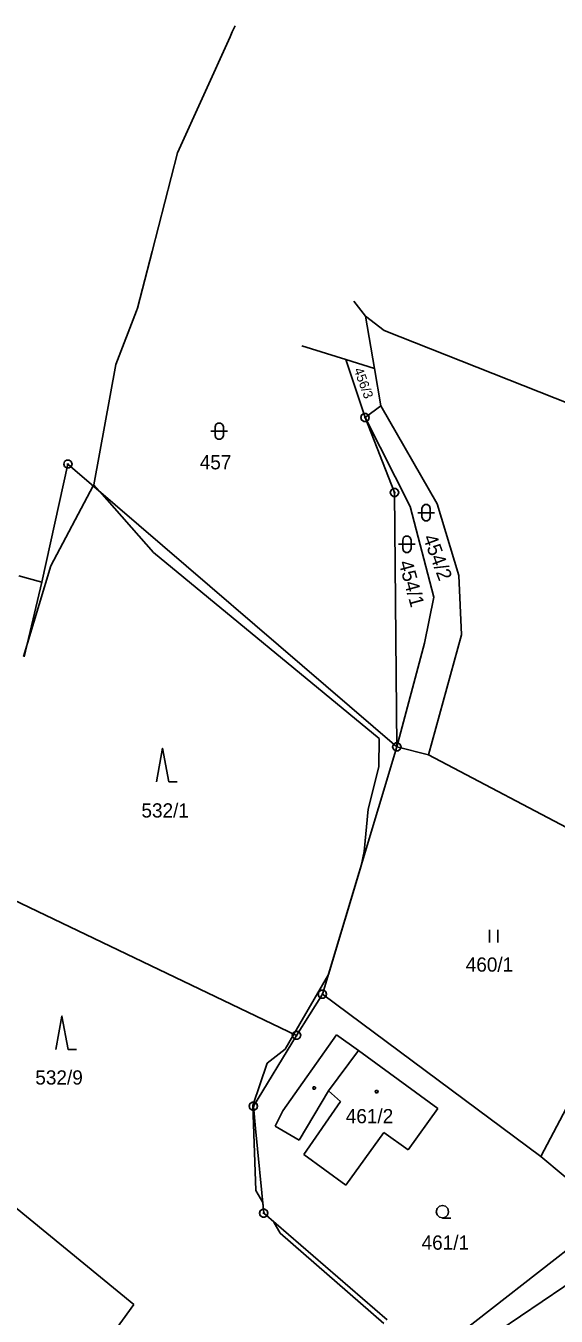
# Model space of a CAD drawing. Extents: x -759699 to -757730, y -1172308 to -1170857.
# Drawn here: x -759346 to -759282.5, y -1171711.2 to -1171556.8 of the extents above; entities that cross this region are included whole.
import ezdxf

# ---------------------------------------------------------------- set-up
doc = ezdxf.new("R2010")
doc.units = 0
for name, color, linetype in [('Vrstva 1', 7, 'Continuous'), ('Vrstva 11', 7, 'Continuous'), ('Vrstva 12', 7, 'Continuous'), ('Vrstva 2', 7, 'Continuous'), ('Vrstva 3', 7, 'Continuous'), ('Vrstva 4', 7, 'Continuous'), ('Vrstva 5', 7, 'Continuous'), ('Vrstva 8', 7, 'Continuous')]:
    doc.layers.add(name, color=color, linetype=linetype)

msp = doc.modelspace()

# ---------------------------------------------------------------- linework, layer by layer
at = {"layer": 'Vrstva 1'}
for p, q in [((-759305.37, -1171591.53), (-759306.74, -1171589.73)), ((-759306.74, -1171589.73), (-759306.74, -1171589.73)), ((-759303.12, -1171593.25), (-759305.37, -1171591.53)), ((-759305.37, -1171591.53), (-759304.29, -1171597.77)), ((-759264.92, -1171608.32), (-759303.12, -1171593.25)), ((-759312.98, -1171595.07), (-759312.98, -1171595.07)), ((-759312.98, -1171595.07), (-759307.69, -1171596.71)), ((-759307.69, -1171596.71), (-759304.29, -1171597.77)), ((-759307.69, -1171596.71), (-759305.41, -1171603.65)), ((-759304.29, -1171597.77), (-759303.52, -1171602.24)), ((-759303.52, -1171602.24), (-759305.41, -1171603.65)), ((-759303.52, -1171602.24), (-759296.79, -1171613.99)), ((-759305.41, -1171603.65), (-759300.01, -1171614.29)), ((-759305.41, -1171603.65), (-759305.41, -1171603.65)), ((-759301.87, -1171612.63), (-759305.41, -1171603.65)), ((-759344.12, -1171623.36), (-759340.98, -1171609.22)), ((-759340.98, -1171609.22), (-759340.98, -1171609.22)), ((-759340.98, -1171609.22), (-759301.6, -1171643.07)), ((-759301.6, -1171643.07), (-759301.87, -1171612.63)), ((-759296.79, -1171613.99), (-759294.16, -1171622.56)), ((-759300.01, -1171614.29), (-759297.16, -1171625.13)), ((-759346.22, -1171632.28), (-759344.12, -1171623.36)), ((-759294.16, -1171622.56), (-759293.86, -1171629.64)), ((-759297.16, -1171625.13), (-759298.3, -1171630.66)), ((-759298.3, -1171630.66), (-759301.6, -1171643.07)), ((-759293.86, -1171629.64), (-759297.81, -1171644)), ((-759310.51, -1171672.66), (-759301.6, -1171643.07)), ((-759297.81, -1171644), (-759301.6, -1171643.07)), ((-759297.81, -1171644), (-759262.18, -1171662.76)), ((-759351.15, -1171659.61), (-759313.61, -1171677.58)), ((-759310.51, -1171672.66), (-759313.61, -1171677.58)), ((-759284.37, -1171692.06), (-759310.51, -1171672.66)), ((-759276.45, -1171677.04), (-759284.37, -1171692.06)), ((-759313.61, -1171677.58), (-759318.78, -1171686.06)), ((-759308.84, -1171677.53), (-759315.24, -1171686.62)), ((-759306.2, -1171679.4), (-759308.84, -1171677.53)), ((-759296.68, -1171686.34), (-759306.2, -1171679.4)), ((-759364.55, -1171684.03), (-759333.09, -1171709.78)), ((-759313.29, -1171690.11), (-759309.78, -1171684.21)), ((-759309.78, -1171684.21), (-759308.36, -1171685.47)), ((-759318.78, -1171686.06), (-759318.52, -1171688.73)), ((-759315.24, -1171686.62), (-759316.16, -1171688.43)), ((-759308.36, -1171685.47), (-759312.73, -1171691.84)), ((-759300.26, -1171691.26), (-759296.68, -1171686.34)), ((-759318.52, -1171688.73), (-759317.54, -1171698.86)), ((-759316.16, -1171688.43), (-759313.29, -1171690.11)), ((-759307.7, -1171695.48), (-759303.17, -1171689.21)), ((-759303.17, -1171689.21), (-759300.26, -1171691.26)), ((-759312.73, -1171691.84), (-759307.7, -1171695.48)), ((-759284.37, -1171692.06), (-759275.95, -1171699.14)), ((-759317.54, -1171698.86), (-759302.74, -1171711.62)), ((-759297.8, -1171716.13), (-759275.95, -1171699.14)), ((-759347.86, -1171730.08), (-759333.09, -1171709.78))]:
    msp.add_line(p, q, dxfattribs=at)
at = {"layer": 'Vrstva 11'}
for p, q in [((-759320.97, -1171556.78), (-759321.31, -1171557.52)), ((-759321.57, -1171558.1), (-759327.86, -1171571.97)), ((-759321.31, -1171557.52), (-759321.57, -1171558.1)), ((-759327.86, -1171571.97), (-759330.91, -1171583.8)), ((-759330.91, -1171583.8), (-759332.05, -1171588.24)), ((-759332.05, -1171588.24), (-759332.65, -1171590.56)), ((-759332.76, -1171590.87), (-759335.24, -1171597.32)), ((-759332.65, -1171590.56), (-759332.76, -1171590.87)), ((-759335.24, -1171597.32), (-759337.88, -1171611.7)), ((-759343.03, -1171621.39), (-759337.95, -1171611.83)), ((-759337.95, -1171611.83), (-759337.88, -1171611.7)), ((-759337.88, -1171611.7), (-759337.17, -1171612.49)), ((-759337.17, -1171612.49), (-759330.72, -1171619.8)), ((-759330.72, -1171619.8), (-759303.72, -1171642.05)), ((-759345.84, -1171630.65), (-759343.03, -1171621.39)), ((-759346.32, -1171632.25), (-759345.84, -1171630.65)), ((-759303.72, -1171642.05), (-759303.74, -1171645.43)), ((-759303.74, -1171645.43), (-759305.05, -1171650.5)), ((-759305.05, -1171650.5), (-759305.5, -1171655.58)), ((-759305.5, -1171655.58), (-759305.88, -1171657.29)), ((-759305.88, -1171657.29), (-759309.8, -1171670.29)), ((-759309.8, -1171670.29), (-759313.94, -1171677.42)), ((-759313.94, -1171677.42), (-759314.99, -1171679.22)), ((-759314.99, -1171679.22), (-759317.12, -1171680.9)), ((-759317.12, -1171680.9), (-759318.85, -1171685.97)), ((-759318.85, -1171685.97), (-759318.5, -1171696.13)), ((-759318.5, -1171696.13), (-759317.66, -1171697.58)), ((-759317.66, -1171697.58), (-759317.54, -1171698.86)), ((-759317.54, -1171698.86), (-759316.33, -1171699.91)), ((-759316.33, -1171699.91), (-759315.56, -1171701.24)), ((-759315.56, -1171701.24), (-759303.17, -1171712.06))]:
    msp.add_line(p, q, dxfattribs=at)
at = {"layer": 'Vrstva 12'}
for p, q in [((-759309.78, -1171684.21), (-759306.2, -1171679.4)), ((-759296.68, -1171686.34), (-759306.2, -1171679.4)), ((-759309.78, -1171684.21), (-759308.36, -1171685.47)), ((-759308.36, -1171685.47), (-759312.73, -1171691.84)), ((-759300.26, -1171691.26), (-759296.68, -1171686.34)), ((-759307.7, -1171695.48), (-759303.17, -1171689.21)), ((-759303.17, -1171689.21), (-759300.26, -1171691.26)), ((-759312.73, -1171691.84), (-759307.7, -1171695.48))]:
    msp.add_line(p, q, dxfattribs=at)
at = {"layer": 'Vrstva 3'}
for p, q in [((-759290.49, -1171664.96), (-759290.49, -1171666.46)), ((-759289.49, -1171666.46), (-759289.49, -1171664.96))]:
    msp.add_line(p, q, dxfattribs=at)
for points in [[(-759323.37, -1171604.78), (-759323.27, -1171604.49), (-759323.02, -1171604.31), (-759322.71, -1171604.31), (-759322.46, -1171604.49), (-759322.36, -1171604.78), (-759322.36, -1171605.78), (-759322.46, -1171606.07), (-759322.71, -1171606.25), (-759323.02, -1171606.25), (-759323.27, -1171606.07), (-759323.37, -1171605.78)], [(-759298.6, -1171614.54), (-759298.5, -1171614.25), (-759298.25, -1171614.07), (-759297.94, -1171614.07), (-759297.69, -1171614.25), (-759297.59, -1171614.54), (-759297.59, -1171615.54), (-759297.69, -1171615.83), (-759297.94, -1171616.01), (-759298.25, -1171616.01), (-759298.5, -1171615.83), (-759298.6, -1171615.54)], [(-759300.9, -1171618.31), (-759300.8, -1171618.02), (-759300.55, -1171617.84), (-759300.24, -1171617.84), (-759299.99, -1171618.02), (-759299.89, -1171618.31), (-759299.89, -1171619.31), (-759299.99, -1171619.6), (-759300.24, -1171619.78), (-759300.55, -1171619.78), (-759300.8, -1171619.6), (-759300.9, -1171619.31)]]:
    msp.add_lwpolyline(points, close=True, dxfattribs=at)
for points in [[(-759323.87, -1171605.28), (-759322.6, -1171605.28), (-759321.87, -1171605.28)], [(-759299.1, -1171615.04), (-759297.83, -1171615.04), (-759297.1, -1171615.04)], [(-759301.4, -1171618.81), (-759300.13, -1171618.81), (-759299.4, -1171618.81)], [(-759330.39, -1171647.23), (-759329.64, -1171643.23), (-759328.89, -1171647.23), (-759327.89, -1171647.23)], [(-759342.45, -1171679.27), (-759341.7, -1171675.27), (-759340.95, -1171679.27), (-759339.95, -1171679.27)], [(-759296.13, -1171699.41), (-759296.51, -1171699.31), (-759296.78, -1171699.04), (-759296.88, -1171698.67), (-759296.78, -1171698.3), (-759296.51, -1171698.03), (-759296.14, -1171697.93), (-759295.77, -1171698.03), (-759295.5, -1171698.3), (-759295.4, -1171698.68), (-759295.5, -1171699.06), (-759295.77, -1171699.33), (-759296.15, -1171699.43), (-759295.15, -1171699.43)]]:
    msp.add_lwpolyline(points, dxfattribs=at)
at = {"layer": 'Vrstva 4'}
for p, q in [((-759346.85, -1171622.58), (-759344.12, -1171623.36)), ((-759309.78, -1171684.21), (-759306.2, -1171679.4)), ((-759296.25, -1171717.55), (-759273.85, -1171702.42))]:
    msp.add_line(p, q, dxfattribs=at)
at = {"layer": 'Vrstva 5'}
for points in [[(-759311.4, -1171683.73), (-759311.31, -1171683.88), (-759311.4, -1171684.03), (-759311.58, -1171684.03), (-759311.67, -1171683.88), (-759311.58, -1171683.73)], [(-759303.93, -1171684.16), (-759303.84, -1171684.31), (-759303.93, -1171684.46), (-759304.11, -1171684.46), (-759304.2, -1171684.31), (-759304.11, -1171684.16)]]:
    msp.add_lwpolyline(points, close=True, dxfattribs=at)
at = {"layer": 'Vrstva 8'}
for p, q in [((-759305.53, -1171603.65), (-759305.29, -1171603.65)), ((-759341.1, -1171609.22), (-759340.86, -1171609.22)), ((-759301.99, -1171612.63), (-759301.75, -1171612.63)), ((-759301.72, -1171643.07), (-759301.48, -1171643.07)), ((-759310.63, -1171672.66), (-759310.39, -1171672.66)), ((-759313.73, -1171677.58), (-759313.49, -1171677.58)), ((-759318.9, -1171686.06), (-759318.66, -1171686.06)), ((-759317.66, -1171698.86), (-759317.42, -1171698.86))]:
    msp.add_line(p, q, dxfattribs=at)
for points in [[(-759305.26, -1171603.17), (-759305.01, -1171603.35), (-759304.91, -1171603.64), (-759305.01, -1171603.93), (-759305.26, -1171604.11), (-759305.57, -1171604.11), (-759305.82, -1171603.93), (-759305.92, -1171603.64), (-759305.82, -1171603.35), (-759305.57, -1171603.17)], [(-759340.83, -1171608.74), (-759340.58, -1171608.92), (-759340.48, -1171609.21), (-759340.58, -1171609.5), (-759340.83, -1171609.68), (-759341.14, -1171609.68), (-759341.39, -1171609.5), (-759341.49, -1171609.21), (-759341.39, -1171608.92), (-759341.14, -1171608.74)], [(-759301.72, -1171612.15), (-759301.47, -1171612.33), (-759301.37, -1171612.62), (-759301.47, -1171612.91), (-759301.72, -1171613.09), (-759302.03, -1171613.09), (-759302.28, -1171612.91), (-759302.38, -1171612.62), (-759302.28, -1171612.33), (-759302.03, -1171612.15)], [(-759301.45, -1171642.59), (-759301.2, -1171642.77), (-759301.1, -1171643.06), (-759301.2, -1171643.35), (-759301.45, -1171643.53), (-759301.76, -1171643.53), (-759302.01, -1171643.35), (-759302.11, -1171643.06), (-759302.01, -1171642.77), (-759301.76, -1171642.59)], [(-759310.36, -1171672.18), (-759310.11, -1171672.36), (-759310.01, -1171672.65), (-759310.11, -1171672.94), (-759310.36, -1171673.12), (-759310.67, -1171673.12), (-759310.92, -1171672.94), (-759311.02, -1171672.65), (-759310.92, -1171672.36), (-759310.67, -1171672.18)], [(-759313.46, -1171677.1), (-759313.21, -1171677.28), (-759313.11, -1171677.57), (-759313.21, -1171677.86), (-759313.46, -1171678.04), (-759313.77, -1171678.04), (-759314.02, -1171677.86), (-759314.12, -1171677.57), (-759314.02, -1171677.28), (-759313.77, -1171677.1)], [(-759318.63, -1171685.58), (-759318.38, -1171685.76), (-759318.28, -1171686.05), (-759318.38, -1171686.34), (-759318.63, -1171686.52), (-759318.94, -1171686.52), (-759319.19, -1171686.34), (-759319.29, -1171686.05), (-759319.19, -1171685.76), (-759318.94, -1171685.58)], [(-759317.39, -1171698.38), (-759317.14, -1171698.56), (-759317.04, -1171698.85), (-759317.14, -1171699.14), (-759317.39, -1171699.32), (-759317.7, -1171699.32), (-759317.95, -1171699.14), (-759318.05, -1171698.85), (-759317.95, -1171698.56), (-759317.7, -1171698.38)]]:
    msp.add_lwpolyline(points, close=True, dxfattribs=at)

# ---------------------------------------------------------------- texts
at = {"layer": 'Vrstva 2'}
for s, height, rotation, p in [('456/3', 1.14, 290.37501, (-759306.773, -1171597.928)), ('454/2', 1.7, 290.43231, (-759298.501, -1171617.99)), ('454/1', 1.7, 285.27569, (-759301.395, -1171620.989))]:
    msp.add_text(s, height=height, rotation=rotation, dxfattribs=at).set_placement(p)
for s, p in [('457', (-759325.201, -1171609.85)), ('532/1', (-759332.183, -1171651.51)), ('460/1', (-759293.352, -1171669.95)), ('532/9', (-759344.891, -1171683.46)), ('461/2', (-759307.719, -1171688.09)), ('461/1', (-759298.637, -1171703.22))]:
    msp.add_text(s, height=1.7, dxfattribs=at).set_placement(p)

doc.saveas('drawing.dxf')
